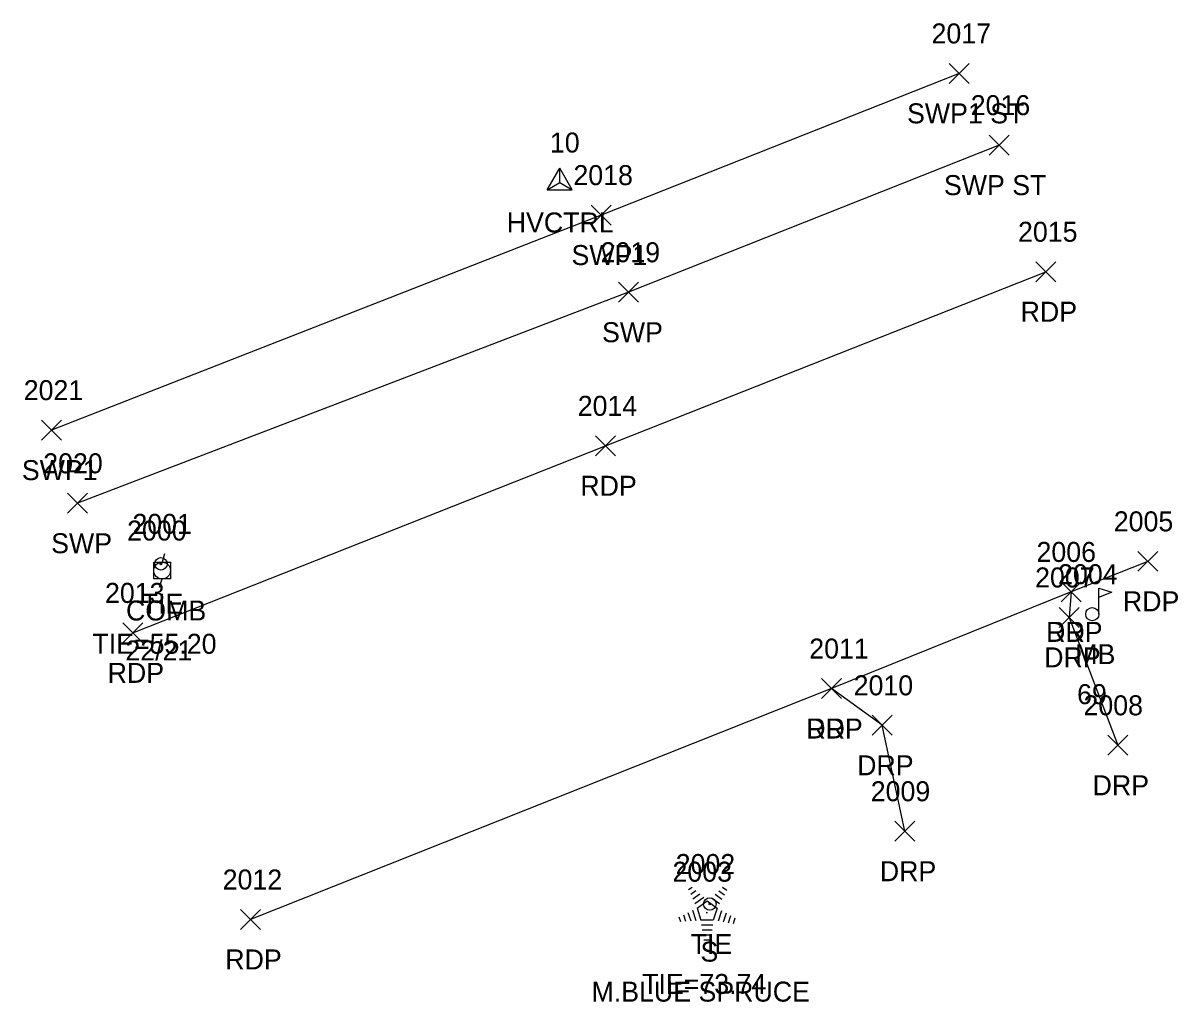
# Model space of a CAD drawing. Extents: x 1497084 to 1499861, y 734741 to 735567.
# Drawn here: x 1497588.7 to 1497704.2, y 735048.8 to 735146.8 of the extents above; entities that cross this region are included whole.
import ezdxf

# ---------------------------------------------------------------- set-up
doc = ezdxf.new("R2010")
doc.units = 0
for name, color, linetype in [('C_A', 7, 'Continuous'), ('C_C', 7, 'Continuous'), ('C_I', 7, 'Continuous'), ('CBP', 7, 'Continuous'), ('CPSM', 7, 'Continuous'), ('L_A', 7, 'Continuous'), ('L_C', 7, 'Continuous'), ('L_I', 7, 'Continuous'), ('LMB', 7, 'Continuous'), ('LTC', 7, 'Continuous'), ('P_A', 7, 'Continuous'), ('P_I', 7, 'Continuous'), ('P_TIC', 7, 'Continuous'), ('PET', 7, 'Continuous'), ('R_A', 7, 'Continuous'), ('R_I', 7, 'Continuous'), ('R_TIC', 7, 'Continuous'), ('RDP', 7, 'Continuous'), ('RSW', 7, 'Continuous'), ('U_A', 7, 'Continuous'), ('U_C', 7, 'Continuous'), ('U_I', 7, 'Continuous'), ('UP', 7, 'Continuous')]:
    doc.layers.add(name, color=color, linetype=linetype)

msp = doc.modelspace()

# ---------------------------------------------------------------- linework, layer by layer
at = {"layer": 'CBP'}
for centre, radius in [((1497602.47, 735092.68), 0.625), ((1497602.47, 735092.68), 0.0833), ((1497657.38, 735058.64), 0.625), ((1497657.38, 735058.64), 0.0833)]:
    msp.add_circle(centre, radius, dxfattribs=at)
at = {"layer": 'CPSM'}
for p, q in [((1497641.12, 735130.12), (1497642.37, 735132.28)), ((1497643.62, 735130.12), (1497642.37, 735132.28)), ((1497642.37, 735130.84), (1497642.37, 735132.28)), ((1497641.12, 735130.12), (1497642.37, 735130.84)), ((1497642.37, 735130.84), (1497642.37, 735130.84)), ((1497642.37, 735130.84), (1497643.62, 735130.12)), ((1497641.12, 735130.12), (1497643.62, 735130.12))]:
    msp.add_line(p, q, dxfattribs=at)
at = {"layer": 'LMB'}
for p, q in [((1497696.28, 735090.24), (1497697.57, 735089.86)), ((1497696.28, 735087.65), (1497696.28, 735090.24)), ((1497696.28, 735089.34), (1497697.56, 735089.85)), ((1497695.63, 735087.64), (1497695.63, 735087.64))]:
    msp.add_line(p, q, dxfattribs=at)
msp.add_circle((1497695.63, 735087.64), 0.656, dxfattribs=at)
at = {"layer": 'LTC'}
for p, q in [((1497655.25, 735060.08), (1497655.61, 735060.33)), ((1497655.46, 735059.61), (1497655.99, 735060)), ((1497658.28, 735059.97), (1497658.83, 735059.57)), ((1497658.65, 735060.32), (1497659.07, 735060.01)), ((1497655.67, 735059.15), (1497656.37, 735059.66)), ((1497655.88, 735058.68), (1497656.76, 735059.32)), ((1497656.1, 735058.22), (1497657.12, 735058.96)), ((1497657.12, 735058.96), (1497658.11, 735058.23)), ((1497657.54, 735059.27), (1497658.35, 735058.68)), ((1497657.91, 735059.62), (1497658.59, 735059.13)), ((1497654.74, 735057.57), (1497654.95, 735056.92)), ((1497655.19, 735057.79), (1497655.47, 735056.95)), ((1497655.65, 735058.01), (1497655.98, 735056.99)), ((1497656.1, 735058.22), (1497656.49, 735057.03)), ((1497658.11, 735058.23), (1497657.72, 735057.03)), ((1497658.55, 735057.96), (1497658.21, 735056.92)), ((1497659, 735057.71), (1497658.71, 735056.83)), ((1497654.28, 735057.36), (1497654.44, 735056.89)), ((1497657.72, 735057.03), (1497656.49, 735057.03)), ((1497657.68, 735056.53), (1497656.54, 735056.53)), ((1497659.44, 735057.46), (1497659.2, 735056.73)), ((1497659.88, 735057.21), (1497659.7, 735056.64)), ((1497657.6, 735056.03), (1497656.61, 735056.03)), ((1497657.52, 735055.53), (1497656.68, 735055.53)), ((1497657.43, 735055.03), (1497656.76, 735055.03))]:
    msp.add_line(p, q, dxfattribs=at)
at = {"layer": 'P_TIC'}
for points in [[(1497689.97, 735120.91), (1497691.97, 735122.91)], [(1497691.97, 735120.91), (1497689.97, 735122.91)], [(1497645.93, 735103.49), (1497647.93, 735105.49)], [(1497647.93, 735103.49), (1497645.93, 735105.49)], [(1497700.2, 735091.93), (1497702.2, 735093.93)], [(1497702.2, 735091.93), (1497700.2, 735093.93)], [(1497692.52, 735088.87), (1497694.52, 735090.87)], [(1497694.52, 735088.87), (1497692.52, 735090.87)], [(1497598.65, 735084.77), (1497600.65, 735086.77)], [(1497600.65, 735084.77), (1497598.65, 735086.77)], [(1497668.53, 735079.2), (1497670.53, 735081.2)], [(1497670.53, 735079.2), (1497668.53, 735081.2)], [(1497610.42, 735056.09), (1497612.42, 735058.09)], [(1497612.42, 735056.09), (1497610.42, 735058.09)]]:
    msp.add_lwpolyline(points, dxfattribs=at)
at = {"layer": 'PET'}
for points in [[(1497599.65, 735085.77), (1497646.93, 735104.49), (1497690.97, 735121.91)], [(1497701.2, 735092.93), (1497693.52, 735089.87), (1497669.53, 735080.2), (1497611.42, 735057.09)]]:
    msp.add_lwpolyline(points, dxfattribs=at)
at = {"layer": 'R_TIC'}
for points in [[(1497681.32, 735140.76), (1497683.32, 735142.76)], [(1497683.32, 735140.76), (1497681.32, 735142.76)], [(1497685.3, 735133.58), (1497687.3, 735135.58)], [(1497687.3, 735133.58), (1497685.3, 735135.58)], [(1497645.5, 735126.58), (1497647.5, 735128.58)], [(1497647.5, 735126.58), (1497645.5, 735128.58)], [(1497648.23, 735118.86), (1497650.23, 735120.86)], [(1497650.23, 735118.86), (1497648.23, 735120.86)], [(1497590.52, 735105.06), (1497592.52, 735107.06)], [(1497592.52, 735105.06), (1497590.52, 735107.06)], [(1497593.13, 735097.74), (1497595.13, 735099.74)], [(1497595.13, 735097.74), (1497593.13, 735099.74)], [(1497692.52, 735088.87), (1497694.52, 735090.87)], [(1497694.52, 735088.87), (1497692.52, 735090.87)], [(1497692.33, 735086.32), (1497694.33, 735088.32)], [(1497694.33, 735086.32), (1497692.33, 735088.32)], [(1497668.53, 735079.2), (1497670.53, 735081.2)], [(1497670.53, 735079.2), (1497668.53, 735081.2)], [(1497673.62, 735075.52), (1497675.62, 735077.52)], [(1497675.62, 735075.52), (1497673.62, 735077.52)], [(1497697.17, 735073.52), (1497699.17, 735075.52)], [(1497699.17, 735073.52), (1497697.17, 735075.52)], [(1497675.89, 735064.92), (1497677.89, 735066.92)], [(1497677.89, 735064.92), (1497675.89, 735066.92)]]:
    msp.add_lwpolyline(points, dxfattribs=at)
at = {"layer": 'RDP'}
for points in [[(1497693.52, 735089.87), (1497693.33, 735087.32), (1497698.17, 735074.52)], [(1497676.89, 735065.92), (1497674.62, 735076.52), (1497669.53, 735080.2)]]:
    msp.add_lwpolyline(points, dxfattribs=at)
at = {"layer": 'RSW'}
for points in [[(1497682.32, 735141.76), (1497646.5, 735127.58), (1497591.52, 735106.06)], [(1497686.3, 735134.58), (1497649.23, 735119.86), (1497594.13, 735098.74)]]:
    msp.add_lwpolyline(points, dxfattribs=at)
at = {"layer": 'UP'}
for p, q in [((1497602.84, 735093.68), (1497602.59, 735092.85)), ((1497601.76, 735091.18), (1497601.76, 735092.85)), ((1497601.76, 735092.85), (1497603.42, 735092.85)), ((1497603.42, 735092.85), (1497603.42, 735091.18)), ((1497603.42, 735091.18), (1497601.76, 735091.18)), ((1497602.34, 735090.35), (1497602.59, 735091.18)), ((1497602.59, 735092.01), (1497602.59, 735092.01))]:
    msp.add_line(p, q, dxfattribs=at)
msp.add_circle((1497602.59, 735092.01), 0.833, dxfattribs=at)

# ---------------------------------------------------------------- texts
at = {"layer": 'C_A'}
for s, p in [('HVCTRL', (1497637.06, 735125.84)), ('TIE', (1497600.55, 735087.68)), ('TIE', (1497655.46, 735053.64))]:
    msp.add_text(s, height=2, dxfattribs=at).set_placement(p)
at = {"layer": 'C_C'}
for s, p in [('TIE=55.20', (1497595.62, 735083.68)), ('TIE=73.74', (1497650.61, 735049.64))]:
    msp.add_text(s, height=2, dxfattribs=at).set_placement(p)
at = {"layer": 'C_I'}
for s, p in [('10', (1497641.38, 735133.84)), ('2001', (1497599.62, 735095.68)), ('2002', (1497653.96, 735061.64))]:
    msp.add_text(s, height=2, dxfattribs=at).set_placement(p)
at = {"layer": 'L_A'}
for s, p in [('MB', (1497693.93, 735082.64)), ('S', (1497656.44, 735052.87))]:
    msp.add_text(s, height=2, dxfattribs=at).set_placement(p)
at = {"layer": 'L_C'}
for s, p in [('69', (1497694.11, 735078.64)), ('M.BLUE SPRUCE', (1497645.54, 735048.87))]:
    msp.add_text(s, height=2, dxfattribs=at).set_placement(p)
at = {"layer": 'L_I'}
for s, p in [('2004', (1497692.21, 735090.64)), ('2003', (1497653.64, 735060.87))]:
    msp.add_text(s, height=2, dxfattribs=at).set_placement(p)
at = {"layer": 'LTC'}
msp.add_text('.', height=1.04, rotation=270, dxfattribs=at).set_placement((1497657, 735057.97))
at = {"layer": 'P_A'}
for p in [(1497688.46, 735116.91), (1497644.42, 735099.49), (1497698.69, 735087.93), (1497691.01, 735084.87), (1497597.14, 735080.77), (1497667.02, 735075.2), (1497608.91, 735052.09)]:
    msp.add_text('RDP', height=2, dxfattribs=at).set_placement(p)
at = {"layer": 'P_I'}
for s, p in [('2015', (1497688.2, 735124.91)), ('2014', (1497644.16, 735107.49)), ('2005', (1497697.78, 735095.93)), ('2006', (1497690.05, 735092.87)), ('2013', (1497596.88, 735088.77)), ('2011', (1497667.32, 735083.2)), ('2012', (1497608.65, 735060.09))]:
    msp.add_text(s, height=2, dxfattribs=at).set_placement(p)
at = {"layer": 'R_A'}
for s, p in [('SWP1 ST', (1497677.1, 735136.76)), ('SWP ST', (1497680.79, 735129.58)), ('SWP1', (1497643.54, 735122.58)), ('SWP', (1497646.59, 735114.86)), ('SWP1', (1497588.56, 735101.06)), ('SWP', (1497591.49, 735093.74)), ('DRP', (1497691.01, 735084.87)), ('DRP', (1497690.82, 735082.32)), ('DRP', (1497667.02, 735075.2)), ('DRP', (1497672.11, 735071.52)), ('DRP', (1497695.66, 735069.52)), ('DRP', (1497674.38, 735060.92))]:
    msp.add_text(s, height=2, dxfattribs=at).set_placement(p)
at = {"layer": 'R_I'}
for s, p in [('2017', (1497679.55, 735144.76)), ('2016', (1497683.47, 735137.58)), ('2018', (1497643.73, 735130.58)), ('2019', (1497646.45, 735122.86)), ('2021', (1497588.75, 735109.06)), ('2020', (1497590.7, 735101.74)), ('2006', (1497690.05, 735092.87)), ('2007', (1497689.91, 735090.32)), ('2011', (1497667.32, 735083.2)), ('2010', (1497671.76, 735079.52)), ('2008', (1497694.75, 735077.52)), ('2009', (1497673.47, 735068.92))]:
    msp.add_text(s, height=2, dxfattribs=at).set_placement(p)
at = {"layer": 'U_A'}
msp.add_text('COMB', height=2, dxfattribs=at).set_placement((1497598.98, 735087.01))
at = {"layer": 'U_C'}
msp.add_text('22/21', height=2, dxfattribs=at).set_placement((1497598.92, 735083.01))
at = {"layer": 'U_I'}
msp.add_text('2000', height=2, dxfattribs=at).set_placement((1497599.09, 735095.01))

doc.saveas('drawing.dxf')
